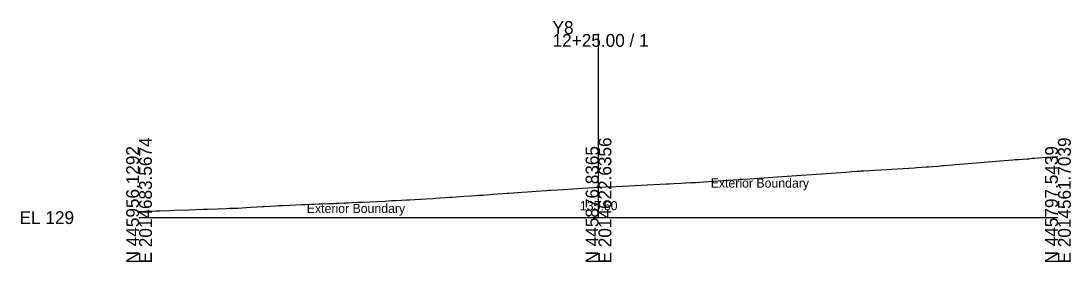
# Model space of a CAD drawing. Extents: x -26 to 1403, y -10 to 8043.
# Drawn here: x -25.7 to 202.8, y 4490.3 to 4542.9 of the extents above; entities that cross this region are included whole.
import ezdxf

# ---------------------------------------------------------------- set-up
doc = ezdxf.new("R2010")
doc.units = 0
for name, color, linetype in [('Default', 7, 'Continuous'), ('Exist Cross Section Cell', 7, 'Continuous'), ('Exist XS Center Line Elevation Label', 7, 'Continuous'), ('Exist XS Ground Line', 7, 'Continuous'), ('Scratch_Level_0', 7, 'Continuous')]:
    doc.layers.add(name, color=color, linetype=linetype)

msp = doc.modelspace()

# ---------------------------------------------------------------- linework, layer by layer
at = {"layer": 'Exist Cross Section Cell'}
for p, q in [((100, 4500), (100, 4540.05)), ((0, 4500), (100, 4500)), ((100, 4500), (200, 4500))]:
    msp.add_line(p, q, dxfattribs=at)
at = {"layer": 'Exist XS Ground Line'}
msp.add_lwpolyline([(0, 4501.35), (1.32, 4501.39), (2.56, 4501.43), (3.66, 4501.48), (4.52, 4501.5), (6.67, 4501.57), (7.61, 4501.6), (10.82, 4501.71), (13.95, 4501.82), (14.88, 4501.85), (17.08, 4501.94), (18.97, 4502.01), (19.7, 4502.04), (20.26, 4502.06), (21.48, 4502.09), (23.42, 4502.19), (24.38, 4502.25), (26.85, 4502.41), (27.21, 4502.44), (29.72, 4502.6), (30.4, 4502.63), (31.28, 4502.67), (32.85, 4502.74), (35.35, 4502.85), (35.99, 4502.87), (37.54, 4502.92), (39.15, 4502.99), (39.57, 4503), (41.1, 4503.05), (42.29, 4503.1), (42.89, 4503.12), (43.65, 4503.16), (44.68, 4503.2), (45.48, 4503.24), (46.45, 4503.28), (47.69, 4503.34), (48.64, 4503.39), (51.76, 4503.54), (53.56, 4503.62), (54.96, 4503.7), (55.38, 4503.72), (55.91, 4503.75), (57.15, 4503.8), (58.11, 4503.86), (58.92, 4503.9), (60, 4503.95), (61.25, 4504.02), (62.48, 4504.09), (64.08, 4504.19), (64.42, 4504.21), (65.53, 4504.29), (67.55, 4504.43), (68.17, 4504.47), (70.68, 4504.66), (72.36, 4504.78), (73.21, 4504.84), (73.85, 4504.88), (74.91, 4504.91), (76.43, 4505.06), (76.99, 4505.1), (79.04, 4505.23), (80.14, 4505.31), (80.45, 4505.33), (83.31, 4505.53), (84.56, 4505.62), (86.46, 4505.75), (88.65, 4505.91), (89.19, 4505.95), (89.59, 4505.97), (92.33, 4506.16), (95.45, 4506.34), (100.18, 4506.61), (101.59, 4506.68), (103.82, 4506.81), (106.59, 4506.96), (114.7, 4507.4), (115.35, 4507.4), (116.39, 4507.45), (118.02, 4507.53), (119.86, 4507.64), (121.09, 4507.67), (122.86, 4507.77), (128.22, 4508.15), (130.43, 4508.28), (131.45, 4508.38), (132.93, 4508.47), (139.97, 4508.97), (153.8, 4509.94), (155.23, 4510.05), (156.24, 4510.12), (156.78, 4510.16), (157.08, 4510.18), (157.76, 4510.23), (168.8, 4510.89), (169.3, 4510.92), (171.31, 4511.04), (171.84, 4511.07), (172.71, 4511.17), (173.82, 4511.25), (174.88, 4511.38), (175.27, 4511.38), (177.05, 4511.52), (177.64, 4511.58), (182.29, 4511.94), (187.33, 4512.38), (190.2, 4512.6), (190.68, 4512.66), (191.5, 4512.71), (193.2, 4512.83), (193.64, 4512.83), (194.37, 4512.93), (194.92, 4512.97), (197.55, 4513.18), (200, 4513.35)], dxfattribs=at)

# ---------------------------------------------------------------- texts
at = {"layer": 'Default'}
msp.add_text('-', height=0.0001, dxfattribs=at).set_placement((0, 4500))
at = {"layer": 'Exist Cross Section Cell'}
for s, p in [('Y8', (90, 4540.05)), ('12+25.00 / 1', (90, 4537.25)), ('EL 129', (-26, 4498.6))]:
    msp.add_text(s, height=2.8, dxfattribs=at).set_placement(p)
for s, p in [('E 2014683.5674', (2.8, 4490)), ('E 2014622.6356', (102.8, 4490)), ('E 2014561.7039', (202.8, 4490)), ('N 445956.1292', (0, 4490)), ('N 445876.8365', (100, 4490)), ('N 445797.5439', (200, 4490))]:
    msp.add_text(s, height=2.8, rotation=90, dxfattribs=at).set_placement(p)
at = {"layer": 'Exist XS Center Line Elevation Label'}
msp.add_text('135.60', height=2, dxfattribs=at).set_placement((95.95, 4501.6))
at = {"layer": 'Scratch_Level_0'}
for p in [(124.42, 4506.54), (36.51, 4501)]:
    msp.add_text('Exterior Boundary', height=2, dxfattribs=at).set_placement(p)

doc.saveas('drawing.dxf')
